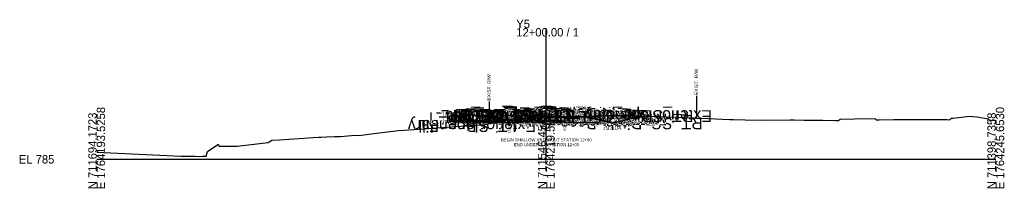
# Model space of a CAD drawing. Extents: x -26 to 303, y -10 to 4039.
# Drawn here: x -25.7 to 302.8, y 1990.3 to 2046.7 of the extents above; entities that cross this region are included whole.
import ezdxf

# ---------------------------------------------------------------- set-up
doc = ezdxf.new("R2010")
doc.units = 0
for name, color, linetype in [('Default', 7, 'Continuous'), ('Exist CMT Pavement', 7, 'Continuous'), ('Exist Cross Section Cell', 7, 'Continuous'), ('Exist XS Center Line Elevation Label', 7, 'Continuous'), ('Exist XS Ground Line', 7, 'Continuous'), ('Old_Level_10', 7, 'Continuous'), ('Prop CMT Pvmt Course 1', 7, 'Continuous'), ('Prop CMT Pvmt Course 3', 7, 'Continuous'), ('Prop CMT Pvmt Surface', 7, 'Continuous'), ('Prop CMT Pvmt Surface Shoulder', 7, 'Continuous'), ('Prop CMT Shld Paved Course 1', 7, 'Continuous'), ('Prop CMT Shld Paved Course 3', 7, 'Continuous'), ('Prop CMT Slope Grass', 7, 'Continuous'), ('Prop CMT Subgrade Earthwork', 7, 'Continuous'), ('Prop Road Sect_ Recs - UC (Outline)', 7, 'Continuous'), ('Prop Road Sect_ Recs - UC (Tx)', 7, 'Continuous'), ('Prop Shade Light', 7, 'Continuous'), ('Prop XS Ditch Standard Text', 7, 'Continuous'), ('Prop XS Earthwork Shape', 7, 'Continuous'), ('Prop XS Earthwork Unsuitable Unclassified', 7, 'Continuous'), ('Prop XS SE Text', 7, 'Continuous'), ('Prop XS Side Slope Text', 7, 'Continuous'), ('Prop XS Wedging', 7, 'Continuous'), ('Scratch_Level_4', 7, 'Continuous')]:
    doc.layers.add(name, color=color, linetype=linetype)

msp = doc.modelspace()

# ---------------------------------------------------------------- linework, layer by layer
at = {"layer": 'Exist CMT Pavement'}
msp.add_lwpolyline([(140, 2013.51), (142.04, 2013.63), (142.59, 2013.66), (145.17, 2013.82), (147.29, 2013.9), (147.67, 2013.91), (149.45, 2013.95), (150.21, 2013.96), (151.29, 2013.99), (152.75, 2014.02), (154.37, 2014.05), (155.28, 2014.07), (156.18, 2014.09)], dxfattribs=at)
at = {"layer": 'Exist Cross Section Cell'}
for p, q in [((150, 2000), (150, 2043.85)), ((0, 2000), (150, 2000)), ((150, 2000), (300, 2000))]:
    msp.add_line(p, q, dxfattribs=at)
at = {"layer": 'Exist XS Ground Line'}
msp.add_lwpolyline([(0, 2002.43), (28.11, 2001), (32.85, 2001), (33.76, 2000.99), (35.31, 2001), (36.51, 2001), (36.96, 2002.64), (40.45, 2004.97), (40.67, 2004.92), (40.79, 2004.35), (41.68, 2004.35), (42.92, 2004.35), (44.67, 2004.35), (46.3, 2004.35), (46.88, 2004.34), (57.26, 2005.64), (58.45, 2006.37), (60.99, 2006.54), (70.69, 2007.17), (72.18, 2007.31), (74.03, 2007.41), (74.9, 2007.37), (76.66, 2007.47), (79.4, 2007.64), (81.33, 2007.64), (86.2, 2008.03), (87.74, 2008), (89.11, 2008.14), (93.37, 2008.69), (100.66, 2009.64), (104.1, 2009.82), (112.29, 2010.44), (124.6, 2011.27), (129.01, 2011.55), (130.19, 2011.76), (135.13, 2012.78), (137.58, 2013.27), (138.56, 2013.37), (140.05, 2013.51), (142.04, 2013.63), (142.59, 2013.66), (145.17, 2013.82), (147.29, 2013.9), (147.67, 2013.91), (149.45, 2013.95), (150.21, 2013.96), (151.29, 2013.99), (152.75, 2014.02), (154.37, 2014.05), (155.28, 2014.07), (157.45, 2014.11), (158.08, 2014.13), (159.56, 2014.18), (160.53, 2014.21), (162.9, 2014.29), (163.62, 2014.31), (165.44, 2014.36), (166.71, 2014.39), (167.98, 2014.44), (169.78, 2014.49), (170.52, 2014.52), (173.19, 2014.56), (173.94, 2014.58), (175.77, 2014.61), (176.15, 2014.59), (193.72, 2014.04), (200.09, 2013.76), (203.98, 2013.61), (211.31, 2013.31), (212.44, 2013.27), (216.34, 2013.22), (222.53, 2013.05), (231.39, 2013.17), (232.69, 2013.17), (236.08, 2013.13), (242.26, 2013.05), (246.55, 2012.99), (247.56, 2012.94), (248.07, 2013.44), (252.89, 2013.56), (259.59, 2013.69), (260.1, 2013.19), (260.69, 2013.22), (261.13, 2013.24), (265.94, 2013.3), (269.29, 2013.28), (276.35, 2013.35), (277.33, 2013.34), (283.38, 2013.3), (283.79, 2013.29), (284.71, 2013.23), (285.22, 2013.72), (285.72, 2013.78), (288.53, 2014.07), (291.15, 2014.4), (293.81, 2014.14), (297.5, 2013.49), (298.09, 2012.98), (299.21, 2013.03), (300, 2013.02)], dxfattribs=at)
at = {"layer": 'Old_Level_10'}
for p, q in [((200.1, 2021.16), (200.1, 2013.76)), ((130.91, 2019.31), (130.91, 2011.91)), ((159.99, 2013.86), (152.43, 2014.01)), ((156.18, 2014.07), (156.18, 2012.02)), ((137.58, 2013.27), (137.58, 2011.22))]:
    msp.add_line(p, q, dxfattribs=at)
at = {"layer": 'Prop CMT Pvmt Course 1'}
for points in [[(150, 2014.56), (140, 2014.76)], [(140, 2014.76), (140, 2014.51)], [(150, 2014.31), (140, 2014.51)], [(150, 2014.31), (150, 2014.56)], [(150, 2014.56), (160, 2014.36)], [(150, 2014.44), (150, 2014.31), (150, 2014.31)], [(160, 2014.11), (150, 2014.31)], [(160, 2014.36), (160, 2014.11)]]:
    msp.add_lwpolyline(points, dxfattribs=at)
msp.add_lwpolyline([(150, 2014.31), (150, 2014.44), (150, 2014.44), (150, 2014.31)], close=True, dxfattribs=at)
at = {"layer": 'Prop CMT Pvmt Course 3'}
for points in [[(140, 2014.51), (140, 2014.09)], [(160, 2014.11), (160, 2013.69)], [(156.18, 2013.52), (156.18, 2013.85)], [(156.18, 2013.77), (160, 2013.69)], [(160, 2013.69), (156.18, 2013.77)]]:
    msp.add_lwpolyline(points, dxfattribs=at)
at = {"layer": 'Prop CMT Pvmt Surface'}
for points in [[(150, 2014.56), (140, 2014.76)], [(150, 2014.56), (160, 2014.36)]]:
    msp.add_lwpolyline(points, dxfattribs=at)
at = {"layer": 'Prop CMT Pvmt Surface Shoulder'}
for points in [[(140, 2014.76), (140, 2014.76)], [(160, 2014.36), (160, 2014.36)]]:
    msp.add_lwpolyline(points, dxfattribs=at)
at = {"layer": 'Prop CMT Shld Paved Course 1'}
for points in [[(140, 2014.76), (139.74, 2014.51)], [(139.74, 2014.51), (140, 2014.51)], [(140, 2014.76), (140, 2014.76)], [(140, 2014.51), (140, 2014.76)], [(160, 2014.36), (160, 2014.36)], [(160, 2014.36), (160.26, 2014.11)], [(160, 2014.11), (160, 2014.36)], [(160.26, 2014.11), (160, 2014.11)]]:
    msp.add_lwpolyline(points, dxfattribs=at)
at = {"layer": 'Prop CMT Shld Paved Course 3'}
for points in [[(139.74, 2014.51), (139.32, 2014.08)], [(139.32, 2014.08), (140, 2014.09)], [(140, 2014.51), (139.74, 2014.51)], [(160, 2014.11), (160.26, 2014.11)], [(160.26, 2014.11), (160.68, 2013.68)], [(160.68, 2013.68), (160, 2013.69)], [(160.6, 2013.77), (160.6, 2013.77)]]:
    msp.add_lwpolyline(points, dxfattribs=at)
at = {"layer": 'Prop CMT Slope Grass'}
for points in [[(140, 2014.76), (136, 2014.44), (122.84, 2011.15)], [(160, 2014.36), (164, 2014.04), (172, 2012.04), (181.54, 2014.42)]]:
    msp.add_lwpolyline(points, dxfattribs=at)
at = {"layer": 'Prop CMT Subgrade Earthwork'}
for p, q in [((139.32, 2014.08), (140, 2014.09)), ((140, 2014.09), (140, 2013.5)), ((156.18, 2013.77), (156.18, 2014.09)), ((156.18, 2013.77), (160, 2013.69)), ((160, 2013.69), (160.68, 2013.68))]:
    msp.add_line(p, q, dxfattribs=at)
for points in [[(139.32, 2014.08), (138.74, 2014.66)], [(160.68, 2013.68), (161.26, 2014.26)]]:
    msp.add_lwpolyline(points, dxfattribs=at)
at = {"layer": 'Prop Road Sect_ Recs - UC (Outline)'}
for p, q in [((132.78, 2012.3), (140, 2012.3)), ((140, 2012.3), (140, 2013.5)), ((156.18, 2012.3), (156.18, 2013.52)), ((156.18, 2012.3), (168, 2012.3)), ((168, 2012.3), (168, 2013.04))]:
    msp.add_line(p, q, dxfattribs=at)
at = {"layer": 'Prop Shade Light'}
for p, q in [((161.23, 2014.23), (160.68, 2013.68)), ((132.78, 2012.3), (140, 2012.3)), ((140, 2012.3), (140, 2013.5)), ((160.68, 2013.68), (156.18, 2013.77)), ((156.18, 2013.77), (156.18, 2012.3)), ((156.18, 2012.3), (168, 2012.3)), ((168, 2013.04), (166.94, 2013.3)), ((168, 2012.3), (168, 2013.04))]:
    msp.add_line(p, q, dxfattribs=at)
for points in [[(166.94, 2013.3), (164, 2014.04), (161.23, 2014.23)], [(140, 2013.5), (138.56, 2013.37), (137.58, 2013.27), (135.13, 2012.78), (132.78, 2012.3)]]:
    msp.add_lwpolyline(points, dxfattribs=at)
at = {"layer": 'Prop XS Earthwork Shape'}
for points in [[(122.84, 2011.15), (124.6, 2011.27), (129.01, 2011.55), (130.19, 2011.76), (135.13, 2012.78), (137.58, 2013.27), (138.56, 2013.37), (140, 2013.51), (140, 2014.09), (139.32, 2014.08), (138.74, 2014.66), (136, 2014.44)], [(156.18, 2014.09), (157.45, 2014.11), (158.08, 2014.13), (159.56, 2014.18), (160.53, 2014.21), (161.23, 2014.23), (160.68, 2013.68), (160, 2013.69), (156.18, 2013.77)], [(161.26, 2014.26), (161.5, 2014.24), (161.23, 2014.23)], [(169.78, 2014.49), (170.52, 2014.52), (173.19, 2014.56), (173.94, 2014.58), (175.77, 2014.61), (176.15, 2014.59), (181.54, 2014.42), (172, 2012.04), (164, 2014.04), (161.5, 2014.24), (162.9, 2014.29), (163.62, 2014.31), (165.44, 2014.36), (166.71, 2014.39), (167.98, 2014.44)]]:
    msp.add_lwpolyline(points, close=True, dxfattribs=at)
at = {"layer": 'Prop XS Earthwork Unsuitable Unclassified'}
for p, q in [((160.68, 2013.68), (161.23, 2014.23)), ((172, 2012.04), (181.54, 2014.42)), ((156.18, 2013.77), (160.68, 2013.68)), ((166.94, 2013.3), (172, 2012.04))]:
    msp.add_line(p, q, dxfattribs=at)
for points in [[(161.5, 2014.24), (160.53, 2014.21), (159.56, 2014.18), (158.08, 2014.13), (157.45, 2014.11), (156.18, 2014.09)], [(156.18, 2014.09), (156.18, 2014.07), (156.18, 2013.77)], [(161.23, 2014.23), (164, 2014.04), (166.94, 2013.3)], [(181.54, 2014.42), (176.15, 2014.59), (175.77, 2014.61), (173.94, 2014.58), (173.19, 2014.56), (170.52, 2014.52), (169.78, 2014.49), (167.98, 2014.44), (166.71, 2014.39), (165.44, 2014.36), (163.62, 2014.31), (162.9, 2014.29), (161.5, 2014.24)]]:
    msp.add_lwpolyline(points, dxfattribs=at)
at = {"layer": 'Prop XS Wedging'}
for p, q in [((150, 2014.31), (140, 2014.51)), ((140, 2014.51), (140, 2014.09)), ((140, 2014.09), (140, 2013.5)), ((152.19, 2014.27), (150, 2014.31)), ((151.18, 2015.31), (152.43, 2014.01)), ((152.43, 2014.01), (152.19, 2014.27)), ((156.18, 2014.19), (152.19, 2014.27)), ((152.19, 2014.27), (152.43, 2014.01)), ((155.28, 2014.07), (156.18, 2014.09)), ((156.18, 2014.07), (156.18, 2014.28)), ((156.18, 2014.09), (156.18, 2014.19))]:
    msp.add_line(p, q, dxfattribs=at)
for points in [[(147.29, 2013.9), (147.67, 2013.91), (149.45, 2013.95), (150.21, 2013.96)], [(150.21, 2013.96), (151.29, 2013.99), (152.43, 2014.01)], [(152.43, 2014.01), (152.75, 2014.02), (154.37, 2014.05), (155.28, 2014.07)], [(140, 2013.5), (140.05, 2013.51), (142.04, 2013.63), (142.59, 2013.66)], [(142.59, 2013.66), (145.17, 2013.82), (147.29, 2013.9)]]:
    msp.add_lwpolyline(points, dxfattribs=at)

# ---------------------------------------------------------------- texts
at = {"layer": 'Default'}
msp.add_text('-', height=0.0001, dxfattribs=at).set_placement((0, 2000))
at = {"layer": 'Exist Cross Section Cell'}
for s, p in [('Y5', (140, 2043.85)), ('12+00.00 / 1', (140, 2041.05)), ('EL 785', (-26, 1998.6))]:
    msp.add_text(s, height=2.8, dxfattribs=at).set_placement(p)
for s, p in [('E 1764193.5258', (2.8, 1990)), ('E 1764219.5894', (152.8, 1990)), ('E 1764245.6530', (302.8, 1990)), ('N 711694.1723', (0, 1990)), ('N 711546.4540', (150, 1990)), ('N 711398.7358', (300, 1990))]:
    msp.add_text(s, height=2.8, rotation=90, dxfattribs=at).set_placement(p)
at = {"layer": 'Exist XS Center Line Elevation Label'}
for s, p in [('798.96', (147.86, 2011.96)), ('BEGIN SHALLOW UNDERCUT STATION 12+00', (134.94, 2006))]:
    msp.add_text(s, height=1, dxfattribs=at).set_placement(p)
at = {"layer": 'Old_Level_10'}
for s, height, p in [('EXIST. R/W', 1.181, (131.5, 2019.62)), ('EXIST. R/W', 1.181, (200.69, 2021.46)), ('EOP', 0.787, (137.98, 2008.82)), ('EOP', 0.787, (156.57, 2009.62))]:
    msp.add_text(s, height=height, rotation=90, dxfattribs=at).set_placement(p)
at = {"layer": 'Prop Road Sect_ Recs - UC (Outline)'}
msp.add_text('END UNDERCUT STATION 12+00', height=1, dxfattribs=at).set_placement((139.28, 2004.39))
at = {"layer": 'Prop Road Sect_ Recs - UC (Tx)'}
msp.add_text('END UNDERCUT STATION 12+00', height=1, dxfattribs=at).set_placement((139.28, 2004.4))
at = {"layer": 'Prop XS Ditch Standard Text'}
msp.add_text('797.04', height=1.5, dxfattribs=at).set_placement((168.79, 2009.79))
at = {"layer": 'Prop XS SE Text'}
for p in [(142.4, 2015.71), (152.4, 2015.51)]:
    msp.add_text('0.020', height=1.5, rotation=358.8542, dxfattribs=at).set_placement(p)
at = {"layer": 'Prop XS Side Slope Text'}
for rotation, p in [(14.0362, (128.09, 2013.23)), (345.9638, (167.03, 2014.06)), (14.0362, (175.43, 2013.67))]:
    msp.add_text('4:1', height=1.5, rotation=rotation, dxfattribs=at).set_placement(p)
at = {"layer": 'Scratch_Level_4'}
for s, p in [('LT_GS_OS_CTL', (155.62, 2016.44)), ('LT_PV1_OEEOP', (158.48, 2016.66)), ('LT_PS3_Shelf_Out', (163.59, 2016.17)), ('LT_PV2_OEEOP', (159.49, 2016.53)), ('LT_PV3_OEEOP', (159.52, 2016.2)), ('LT_PV1_OEOT', (157.63, 2016.76)), ('LT_PS1_OEOP', (157.9, 2016.76)), ('LT_PS3_OEOP', (158.35, 2016.17)), ('LT_PS2_OEOP', (158.66, 2016.51)), ('LT_PV2_OEOT', (158.64, 2016.51)), ('LT_PV3_OEOT', (158.67, 2016.18)), ('RT_PV1_OEEOP', (170.2, 2016.44)), ('RT_PV2_OEEOP', (171.21, 2016.31)), ('RT_PV1_IEEOP', (169.32, 2016.44)), ('LT_PV1_IEEOP', (168.82, 2016.44)), ('RT_PV2_IEEOP', (170.33, 2016.31)), ('LT_PV2_IEEOP', (169.82, 2016.31)), ('PV1_PGL', (160.68, 2016.56)), ('PV2_PGL', (161.68, 2016.31)), ('RT_PV1_OEOT', (178.14, 2016.36)), ('RT_PS1_OEOP', (178.41, 2016.36)), ('RT_PV2_OEOT', (179.15, 2016.11)), ('RT_PS2_OEOP', (179.67, 2016.11)), ('RT_GS_OS_CTL', (184.12, 2016.04)), ('Exterior Boundary', (205.31, 2016.42)), ('RT_Slope_Cut', (199.11, 2016.42)), ('Exterior Boundary', (146.62, 2013.15)), ('LT_Slope_Fill', (140.11, 2013.15)), ('LT_Sub_OSS_DLT', (156.01, 2015.7)), ('LT_Sub_Trench_Out', (164.51, 2015.83)), ('LT_Sub_OEEOP', (158.95, 2015.87)), ('LT_Sub_OEOT', (158.11, 2015.84)), ('RT_PV3_OEEOP', (171.24, 2015.98)), ('RT_Sub_OEEOP', (170.67, 2015.64)), ('RT_Sub_Trench_Out', (186.88, 2015.43)), ('RT_PS3_Shelf_Out', (185.28, 2015.77)), ('RT_PV3_OEOT', (179.18, 2015.78)), ('RT_Sub_OEOT', (178.61, 2015.44)), ('RT_PS3_OEOP', (180.04, 2015.77)), ('RT_SS_Ditch_Base_Out', (202.23, 2014.04)), ('RT_Sub_OSS_DLT', (190.4, 2015.3))]:
    msp.add_text(s, height=4, rotation=180, dxfattribs=at).set_placement(p)

doc.saveas('drawing.dxf')
